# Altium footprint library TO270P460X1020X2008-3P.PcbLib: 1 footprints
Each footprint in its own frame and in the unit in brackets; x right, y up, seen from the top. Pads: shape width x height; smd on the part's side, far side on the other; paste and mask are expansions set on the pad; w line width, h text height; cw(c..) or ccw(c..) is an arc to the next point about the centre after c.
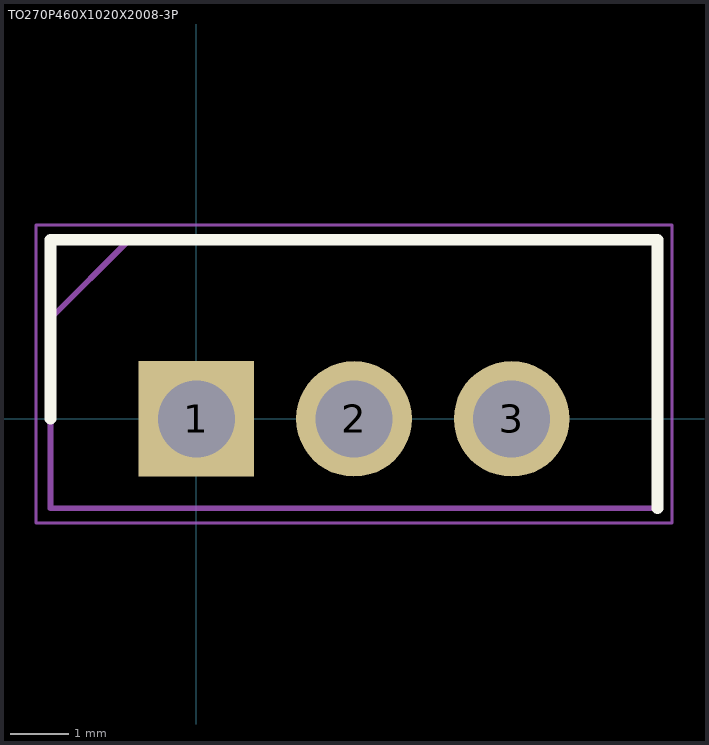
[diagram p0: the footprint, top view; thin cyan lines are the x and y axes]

## TO270P460X1020X2008-3P [mm]
pads (3):
  rect 1.98x1.98 / inner round 1.98 / far side rect 1.98x1.98 hole 1.32: 1(0,0)
  round 1.98 hole 1.32: 2(2.7,0) 3(5.4,0)
Top Overlay:
  lines w0.2: -2.5,0 -2.5,3.069 7.9,3.069 7.9,-1.531
Mechanical 15:
  lines w0.1: -2.5,1.719 -1.15,3.069 ; -2.5,-1.531 7.9,-1.531 7.9,3.069 -2.5,3.069 -2.5,-1.531
Mechanical 20:
  lines w0.05: -2.75,-1.781 8.15,-1.781 8.15,3.319 -2.75,3.319 -2.75,-1.781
